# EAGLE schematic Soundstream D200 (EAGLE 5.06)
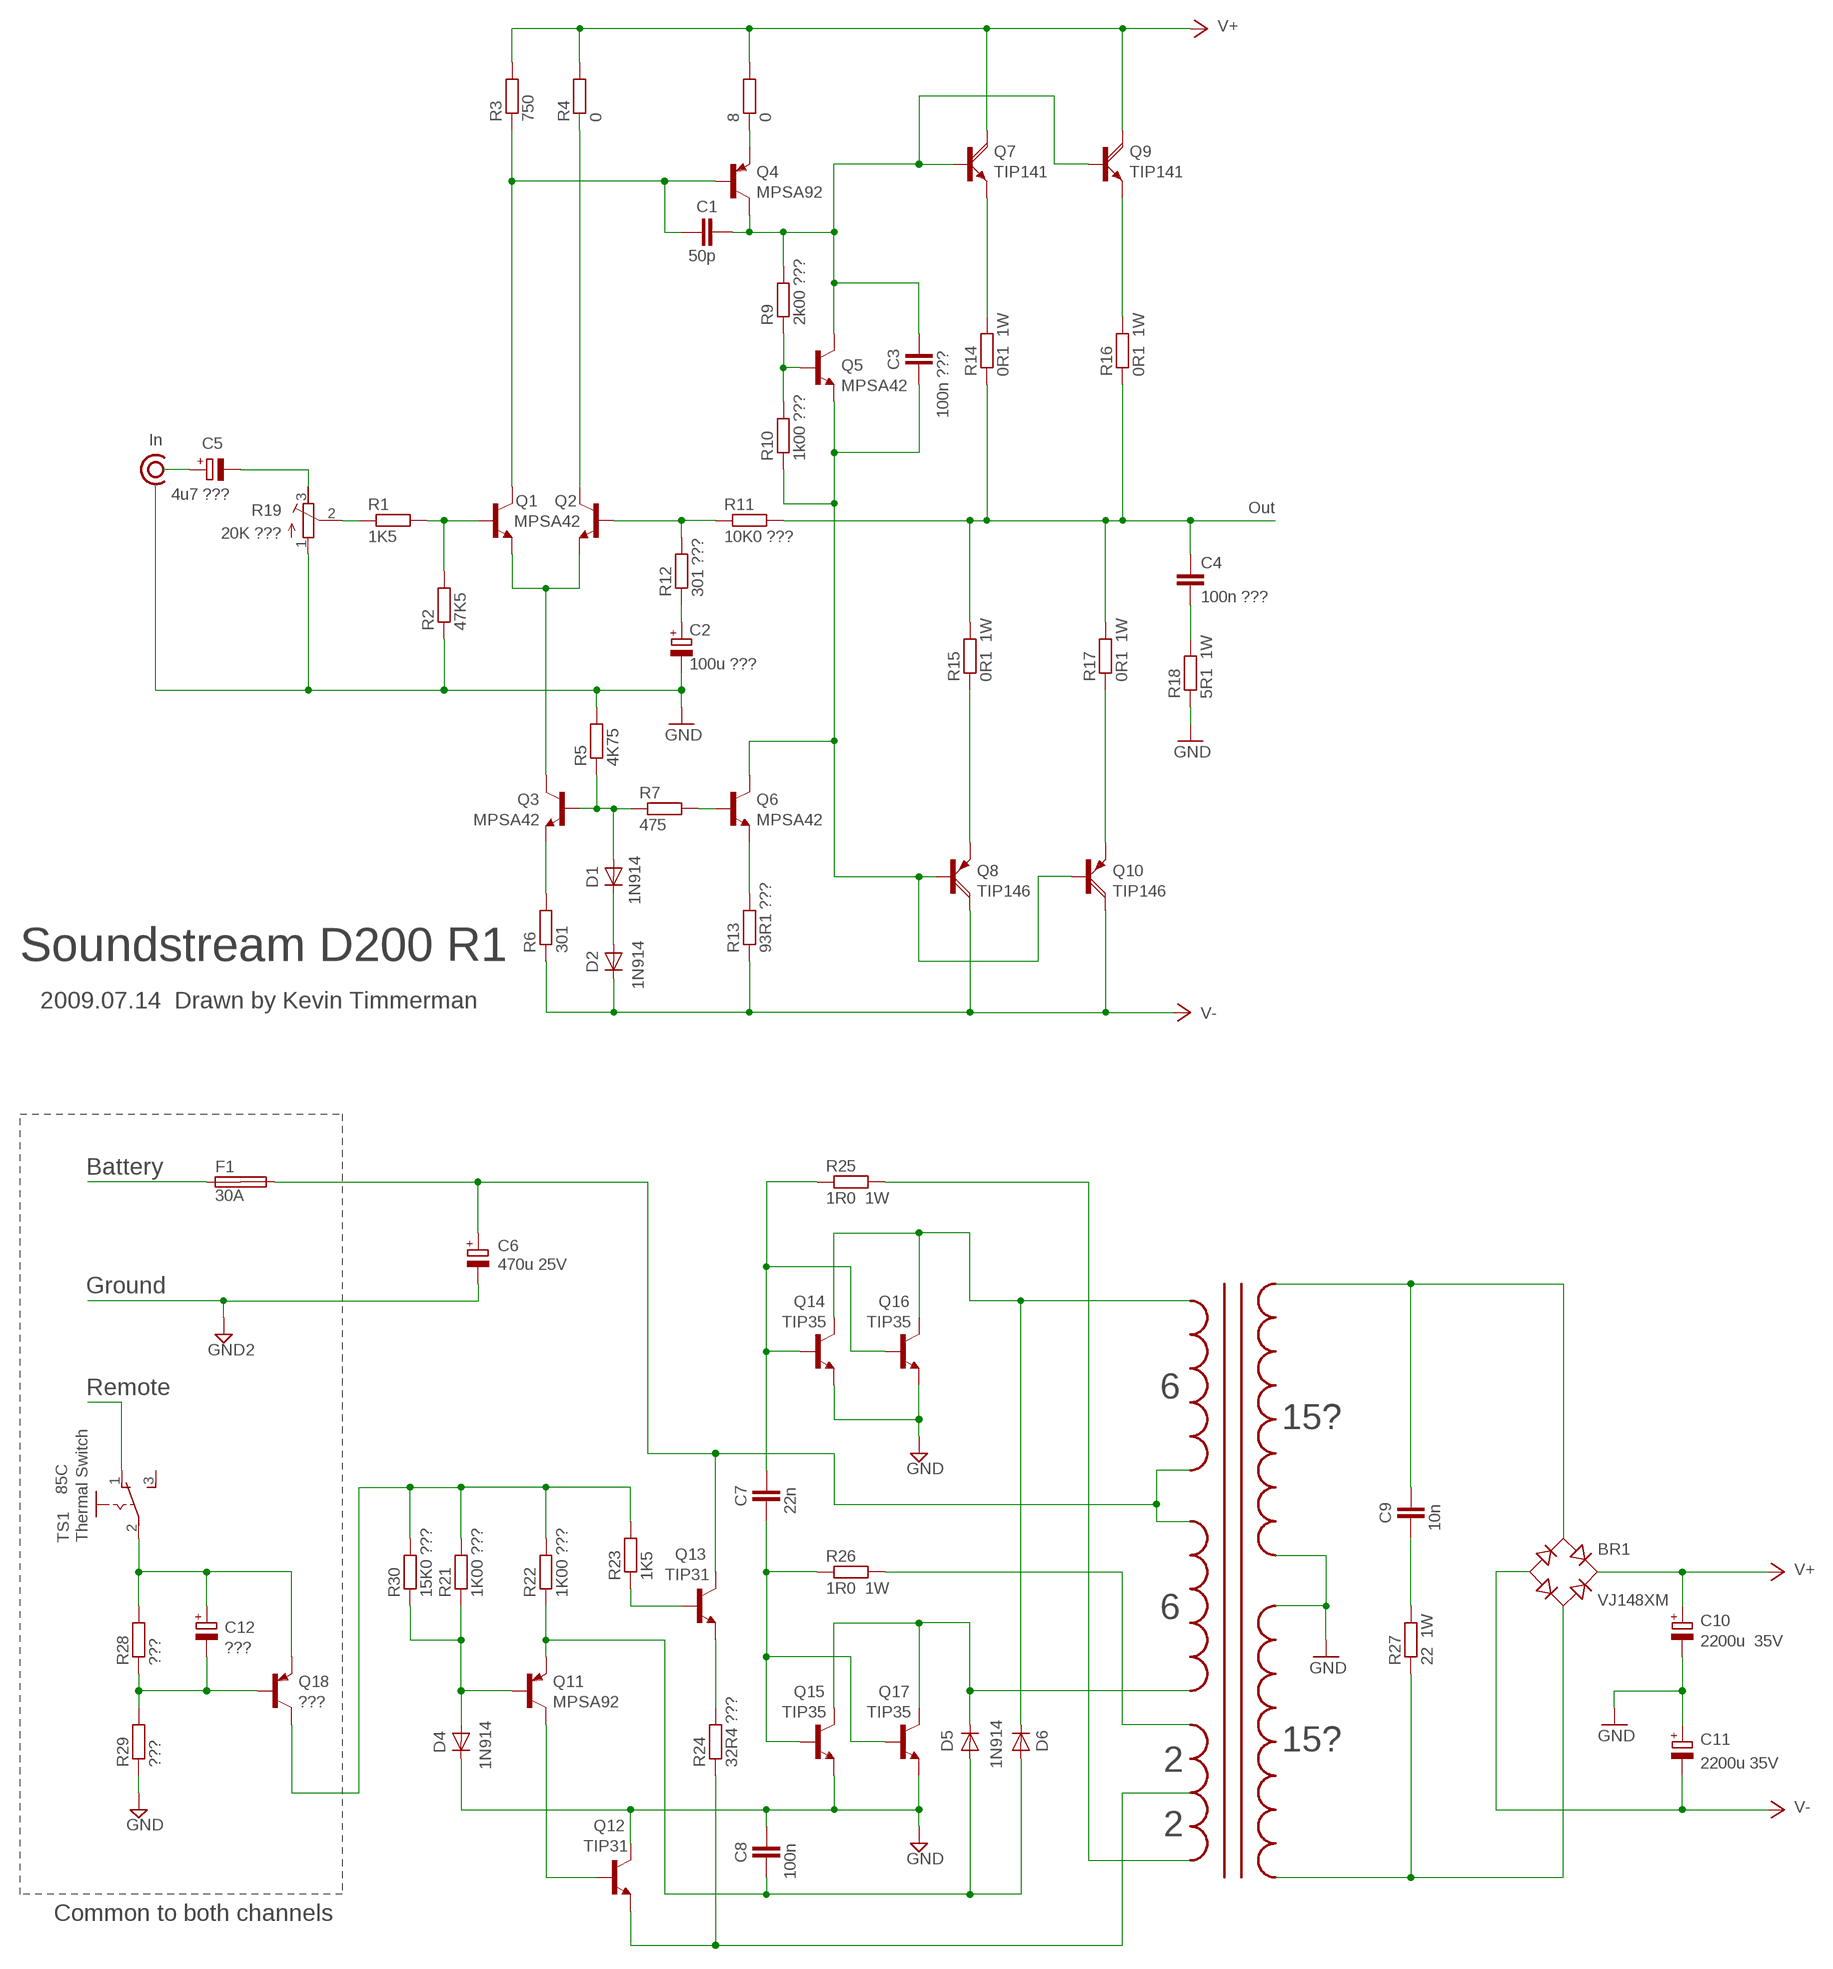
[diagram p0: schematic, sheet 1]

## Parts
8  0  R-EU_0207/10  [0207/10]
BR1  VJ148XM  RECTIFIER-S51  [S51]
C1  50p  C-EU025-025X050  [C025-025X050]
C2  100u ???  CPOL-EUE2.5-5  [E2,5-5]
C3  100n ???  C-EU025-025X050  [C025-025X050]
C4  100n ???  C-EU050-035X075  [C050-035X075]
C5  4u7 ???  CPOL-EUE2.5-5  [E2,5-5]
C6  470u 25V  CPOL-EUE2.5-5  [E2,5-5]
C7  22n  C-EU025-025X050  [C025-025X050]
C8  100n  C-EU025-025X050  [C025-025X050]
C9  10n  C-EU025-025X050  [C025-025X050]
C10  2200u 35V  CPOL-EUE7.5-18  [E7,5-18]
C11  2200u 35V  CPOL-EUE7.5-18  [E7,5-18]
C12  ???  CPOL-EUE2.5-5  [E2,5-5]
D1  1N914  1N4148DO35-10  [DO35-10]
D2  1N914  1N4148DO35-10  [DO35-10]
D4  1N914  1N4148DO35-10  [DO35-10]
D5  1N914  1N4148DO35-10  [DO35-10]
D6  1N914  1N4148DO35-10  [DO35-10]
F1  30A  SHK20Q  [SHK20Q]
Q1  MPSA42  BC337-16-NPN-TO92-EBC  [TO92-EBC]
Q2  MPSA42  BC337-16-NPN-TO92-EBC  [TO92-EBC]
Q3  MPSA42  BC337-16-NPN-TO92-EBC  [TO92-EBC]
Q4  MPSA92  BC448-PNP-TO92-EBC  [TO92-EBC]
Q5  MPSA42  BC337-16-NPN-TO92-EBC  [TO92-EBC]
Q6  MPSA42  BC337-16-NPN-TO92-EBC  [TO92-EBC]
Q7  TIP141  TIP142  [SOT93]
Q8  TIP146  TIP147  [SOT93]
Q9  TIP141  TIP142  [SOT93]
Q10  TIP146  TIP147  [SOT93]
Q11  MPSA92  BC448-PNP-TO92-EBC  [TO92-EBC]
Q12  TIP31  BD243  [TO220]
Q13  TIP31  BD243  [TO220]
Q14  TIP35  BD249  [TOP3]
Q15  TIP35  BD249  [TOP3]
Q16  TIP35  BD249  [TOP3]
Q17  TIP35  BD249  [TOP3]
Q18  ???  BC448-PNP-TO92-EBC  [TO92-EBC]
R1  1K5  R-EU_0207/10  [0207/10]
R2  47K5  R-EU_0207/10  [0207/10]
R3  750  R-EU_0207/10  [0207/10]
R4  0  R-EU_0207/10  [0207/10]
R5  4K75  R-EU_0207/10  [0207/10]
R6  301  R-EU_0207/10  [0207/10]
R7  475  R-EU_0207/10  [0207/10]
R9  2k00 ???  R-EU_0207/10  [0207/10]
R10  1k00 ???  R-EU_0207/10  [0207/10]
R11  10K0 ???  R-EU_0207/10  [0207/10]
R12  301 ???  R-EU_0207/10  [0207/10]
R13  93R1 ???  R-EU_0207/10  [0207/10]
R14  0R1 1W  R-EU_0817/22  [P0817/22]
R15  0R1 1W  R-EU_0817/22  [P0817/22]
R16  0R1 1W  R-EU_0817/22  [P0817/22]
R17  0R1 1W  R-EU_0817/22  [P0817/22]
R18  5R1 1W  R-EU_0817/22  [P0817/22]
R19  20K ???  R-TRIMM3339P  [RTRIM3339P]
R21  1K00 ???  R-EU_0207/10  [0207/10]
R22  1K00 ???  R-EU_0207/10  [0207/10]
R23  1K5  R-EU_0207/10  [0207/10]
R24  32R4 ???  R-EU_0207/10  [0207/10]
R25  1R0 1W  R-EU_0207/10  [0207/10]
R26  1R0 1W  R-EU_0207/10  [0207/10]
R27  22 1W  R-EU_0207/10  [0207/10]
R28  ???  R-EU_0207/10  [0207/10]
R29  ???  R-EU_0207/10  [0207/10]
R30  15K0 ???  R-EU_0207/10  [0207/10]
TS1  Thermal Switch  255SB  [255SB]

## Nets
+5V: BR1.+ BR1.- C10.+ C11.- ; supply symbol labelled V-, V+
GND: C2.- C8.2 C10.- C11.+ D4.C Q12.2(C) Q14.3(E) Q15.3(E) Q16.3(E) Q17.3(E) R2.1 R5.2 R18.1 R19.1(E) R29.1
GND2: C6.- Q18.C R21.2 R22.2 R23.2 R30.2
N$1: Q1.E Q2.E Q3.C
N$2: Q3.E R6.2
N$3: Q6.E R13.2
N$4: C1.1 Q1.C Q4.B R3.1
N$5: D1.C D2.A
N$6: 8.2 Q7.C Q9.C R3.2 R4.2 ; supply symbol labelled V+
N$7: Q10.E R17.1
N$8: D1.A Q3.B R5.1 R7.1
N$9: Q9.E R16.2
N$10: Q6.B R7.2
N$11: C3.1 Q5.E Q6.C Q8.B Q10.B R10.1
N$12: D2.C Q8.C Q10.C R6.1 R13.1 ; supply symbol labelled V-
N$13: Q1.B R1.2 R2.2
N$14: Q2.B R11.1 R12.2
N$15: C5.+
N$16: C1.2 C3.2 Q4.C Q5.C Q7.B Q9.B R9.2
N$17: C4.2 R18.2
N$18: D6.C Q14.2(C) Q16.2(C)
N$19: R25.2
N$20: Q12.3(E) R24.1
N$21: C12.+ Q18.E R28.2 TS1.2(P)
N$22: Q5.B R9.1 R10.2
N$23: C4.1 R11.2 R14.1 R15.2 R16.1 R17.2
N$24: C2.+ R12.1
N$25: D5.C Q15.2(C) Q17.2(C)
N$26: C5.- R19.3(A)
N$27: C8.1 D5.A D6.A Q11.E R22.1
N$28: Q7.E R14.2
N$29: R1.1 R19.2(S)
N$30: Q13.3(E) R24.2
N$31: Q8.E R15.1
N$32: BR1.AC1 C9.2
N$33: BR1.AC2 R27.1
N$34: Q11.C Q12.1(B)
N$35: TS1.1(O)
N$36: D4.A Q11.B R21.1 R30.1
N$37: Q13.1(B) R23.1
N$38: C7.1 Q15.1(B) Q17.1(B) R26.1
N$39: Q2.C R4.1
N$40: 8.1 Q4.E
N$41: C6.+ F1.2A Q13.2(C)
N$42: R26.2
N$43: C7.2 Q14.1(B) Q16.1(B) R25.1
N$44: C9.1 R27.2
N$97: C12.- Q18.B R28.1 R29.2
N$98: F1.1A
Unconnected: F1.1B F1.2B TS1.3(S)

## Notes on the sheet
- In
- Out
- Soundstream D200 R1
- 2009.07.14  Drawn by Kevin Timmerman
- Battery
- Ground
- Remote | 6
- 15?
- 85C
- 6
- 15?
- 2
- 2
- Common to both channels

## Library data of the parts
8 R1-R7 R9-R18 R21-R30 = rcl:R-EU_: RESISTOR, European symbol
BR1 = rectifier:RECTIFIER-: Rectifier
C1 C3 C4 C7-C9 = rcl:C-EU: CAPACITOR, European symbol
C2 C5 C6 C12 = rcl:CPOL-EU: POLARIZED CAPACITOR, European symbol
C10 C11 = resistor:CPOL-EU: POLARIZED CAPACITOR, European symbol
D1 D2 D4-D6 = diode:1N4148: DIODE
F1 = fuse:SHK20Q: FUSE HOLDER 5 x 20 mm, SH contact, E1207 Buerklin 64G6061
Q1-Q3 Q5 Q6 = transistor:*-NPN-: NPN Transistror BF959 corrected 2008.03.06
Q4 Q11 Q18 = transistor:*-PNP-: PNP Transistror
Q7 Q9 = transistor-power:TIP142: NPN DARLINGTON TRANSISTOR
Q8 Q10 = transistor-power:TIP147: PNP DARLINGTON TRANSISTOR
Q12 Q13 = transistor:BD243: NPN TRANSISTOR Source: Motorola Semiconductor, Master Selection Guide Q3/95 SG73 REV 8 page 5.5-4
Q14-Q17 = transistor:BD249: NPN TRANSISTOR
R19 = resistor:R-TRIMM: Trimm resistor
TS1 = switch:255SB: SLIDING SWITCH Distributor Buerklin, 11G810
